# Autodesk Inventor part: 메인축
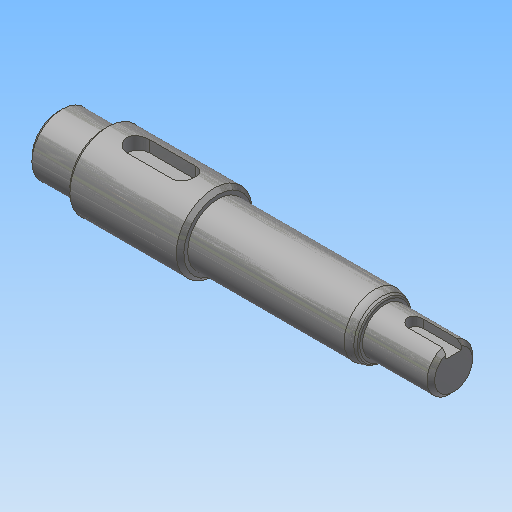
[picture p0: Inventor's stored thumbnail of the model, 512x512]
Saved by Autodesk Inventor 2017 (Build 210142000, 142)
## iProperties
Created: 2019-03
Part Number: 메인축
Material: 강철, 연강
Document SubType Name: Modeling
Designer: mduedu
Density: 1 g/cm^3
Appearance: 강철
Author: mduedu
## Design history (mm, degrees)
sketch "스케치1"
  geometry: L1 (0, 0)-(12, 0); L2 (12, 0)-(12, 8); L3 (12, 8)-(0, 8); L4 (0, 8)-(0, 0); L5 (12, 0)-(42, 0); L6 (42, 0)-(42, 10); L7 (42, 10)-(12, 10); L8 (12, 10)-(12, 0); L9 (42, 0)-(86, 0); L10 (86, 0)-(86, 8); L11 (86, 8)-(42, 8); L12 (42, 8)-(42, 0); L13 (86, 0)-(104, 0); L14 (104, 0)-(104, 6); L15 (104, 6)-(86, 6); L16 (86, 6)-(86, 0)
  constraints: 32 end point, 8 parallel, 4 horizontal, 4 perpendicular
  dimensions: "d0" = 16 diameter of L3 L1; "d2" = 20 diameter of L7 L5; "d3" = 16 diameter of L11 L9; "d4" = 12 diameter of L15 L13; "d5" = 12 distance of L2.end L3.end; "d6" = 30 distance of L6.end L7.end; "d7" = 86 distance between parallel lines of L10 L4; "d8" = 104 distance between parallel lines of L14 L4
revolve "회전1" sketch "스케치1" stored, may be unused: angle "d9" = 90 deg
node "작업 평면1"
sketch "스케치2" dims "d10" = 18
  geometry: L1 (6, -3)-(-6, -3); L2 (-6, -3)-(-6, 3); L3 (-6, 3)-(6, 3); L4 (6, 3)-(6, -3); L5 (15, 10)-(15, -10) reference; 3 further points
  constraints: 8 end point, 2 midpoint, 2 parallel, 2 vertical alignment, 1 horizontal, 1 horizontal alignment, 1 perpendicular, 4 other
  dimensions: "d12" = 6 distance between parallel lines of L3 L1; "d13" = 6 dimension on L5
extrude "돌출1" cut sketch "스케치2" distance "d14" = 3.5; taper "d15" = 0 deg
node "작업 평면2"
sketch "스케치3"
  geometry: L1 (-9, 6)-(-9, -6) reference; L2 (1, -2)-(-9, -2); L3 (1, 2)-(-9, 2); A1 r 2 centre (1, 0) between (1, -2) and (1, 2); 2 further points
  constraints: 4 end point, 2 point on circle, 2 point on line, 2 tangent, 1 centre point, 1 horizontal alignment, 1 midpoint, 1 parallel, 1 perpendicular
  dimensions: "d16" = 12 dimension on A1 L1; "d17" = 4 distance between parallel lines of L3 L2
extrude "돌출2" cut sketch "스케치3" distance "d18" = 2.5; taper "d19" = 0 deg
chamfer "모따기1" distance "d20" = 1; stored, may be unused: second distance "d21" = 2, angle "d22" = 45 deg
chamfer "모따기2" distance "d23" = 1; stored, may be unused: second distance "d24" = 2, angle "d25" = 45 deg
chamfer "모따기3" distance "d26" = 1.73; stored, may be unused: second distance "d27" = 2, angle "d28" = 30 deg
fillet "모깎기2" dims "d31" = 0.5, "d32" = 4
node "솔리드1"
